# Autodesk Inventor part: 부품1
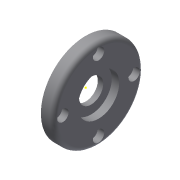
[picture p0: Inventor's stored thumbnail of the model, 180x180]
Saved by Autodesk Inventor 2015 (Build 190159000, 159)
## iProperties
Created: 2019-02
Part Number: 부품1
Material: 일반
Document SubType Name: Modeling
Designer: 5호실-1
Density: 1 g/cm^3
Appearance: 기본값
Author: 5호실-1
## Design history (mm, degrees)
sketch "스케치1"
  geometry: L1 (-3, 19.5)-(-3, 31.5); L2 (-3, 31.5)-(3, 31.5); L3 (-3, 11.5)-(-3, 8.5); L4 (-3, 8.5)-(0.8, 8.5); L5 (0.8, 8.5)-(0.8, 14.5); L6 (0.8, 14.5)-(6, 14.5); L7 (0, 0)-(-6, 0); L8 (-3, 19.5)-(-5, 19.5); L9 (-6, 14.5)-(-6, 18.5); L10 (-6, 18.5)-(-5, 19.5); L11 (6, 14.5)-(6, 28.5); A1 r 3 centre (-6, 11.5) between (-3, 11.5) and (-6, 14.5); A2 r 3 centre (3, 28.5) between (6, 28.5) and (3, 31.5)
  constraints: 22 end point, 5 horizontal, 5 vertical, 4 point on circle, 2 centre point, 1 tangent
  dimensions: "d4" = 6 distance of L1.end L2.end; "d8" = 3 distance of L3.start L3.end; "d9" = 3.8 distance of L3.end L4.end; "d10" = 6 distance of L4.end L5.end; "d11" = 5.2 distance of L5.end L6.end; "d17" = 2 distance of L1.start L8.end; "d18" = 4 distance of L9.start L9.end
revolve "회전1" sketch "스케치1" stored, may be unused: angle "d19" = 90 deg
sketch "스케치2"
  geometry: C1 r 2.25 at (0, 25); C2 r 2.25 at (-25, 0); C3 r 2.25 at (0, -25); C4 r 2.25 at (25, 0); 1 further point
  constraints: 4 centre point
  dimensions: "d21" = 4.5 diameter of C1; "d22" = 4.5 diameter of C2; "d23" = 4.5 diameter of C3; "d24" = 4.5 diameter of C4
extrude "돌출1" cut sketch "스케치2" distance "d25" = 4.4; taper "d26" = 0 deg
sketch "스케치3"
  geometry: C1 r 4 at (0, 25); C2 r 4 at (-25, 0); C3 r 4 at (0, -25); C4 r 4 at (25, 0); A1 r 25 centre (0, 0) between (0, 25) and (-25, 0); 1 further point
  constraints: 5 centre point, 4 point on circle, 1 coincident
  dimensions: "d27" = 50 diameter of A1; "d28" = 8 diameter of C1; "d29" = 8 diameter of C2; "d30" = 8 diameter of C3; "d31" = 8 diameter of C4
extrude "돌출2" cut sketch "스케치3" distance "d32" = 4.6; taper "d33" = 0 deg
sketch "스케치4"
  geometry: 1 further point
node "솔리드1"
